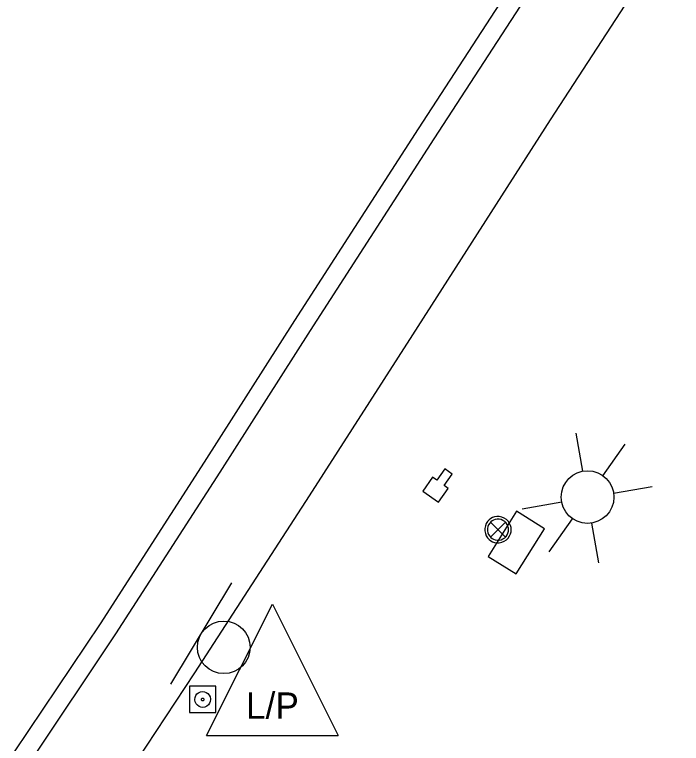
# Model space of a CAD drawing. Extents: x 2161152 to 2175754, y 602179 to 617749.
# Drawn here: x 2162247.2 to 2162297.9, y 604333.2 to 604388.6 of the extents above; entities that cross this region are included whole.
import ezdxf

# ---------------------------------------------------------------- set-up
doc = ezdxf.new("R2010")
doc.units = 0
for name, color, linetype in [('RD_EX_BldgApp_Post', 7, 'Continuous'), ('RD_EX_BldgApp_Sign', 7, 'Continuous'), ('RD_EX_Conc_Curb', 7, 'Continuous'), ('RD_EX_Conc_Gutter', 7, 'Continuous'), ('RD_EX_Conc_Sidewalk', 7, 'Continuous'), ('RD_EX_Misc', 7, 'Continuous'), ('RD_EX_UT', 7, 'Continuous')]:
    doc.layers.add(name, color=color, linetype=linetype)

msp = doc.modelspace()

# ---------------------------------------------------------------- linework, layer by layer
at = {"layer": 'RD_EX_BldgApp_Post'}
for p, q in [((2162284.499, 604348.864), (2162283.365, 604349.999)), ((2162283.365, 604348.864), (2162284.499, 604349.999))]:
    msp.add_line(p, q, dxfattribs=at)
for points in [[(2162284.935, 604349.431), (2162284.923, 604349.586), (2162284.883, 604349.749), (2162284.812, 604349.912), (2162284.707, 604350.068), (2162284.569, 604350.206), (2162284.405, 604350.316), (2162284.222, 604350.391), (2162284.033, 604350.429), (2162283.848, 604350.43), (2162283.676, 604350.401), (2162283.522, 604350.346), (2162283.388, 604350.273), (2162283.262, 604350.177), (2162283.145, 604350.052), (2162283.046, 604349.899), (2162282.973, 604349.723), (2162282.935, 604349.53), (2162282.935, 604349.333), (2162282.973, 604349.14), (2162283.046, 604348.964), (2162283.145, 604348.811), (2162283.262, 604348.686), (2162283.388, 604348.59), (2162283.522, 604348.517), (2162283.676, 604348.462), (2162283.848, 604348.433), (2162284.033, 604348.434), (2162284.222, 604348.472), (2162284.405, 604348.547), (2162284.569, 604348.657), (2162284.707, 604348.795), (2162284.812, 604348.951), (2162284.883, 604349.114), (2162284.923, 604349.277), (2162284.935, 604349.431)], [(2162284.734, 604349.431), (2162284.725, 604349.555), (2162284.693, 604349.685), (2162284.636, 604349.816), (2162284.552, 604349.941), (2162284.442, 604350.051), (2162284.31, 604350.139), (2162284.164, 604350.199), (2162284.013, 604350.229), (2162283.865, 604350.231), (2162283.727, 604350.207), (2162283.604, 604350.163), (2162283.497, 604350.105), (2162283.396, 604350.028), (2162283.302, 604349.928), (2162283.223, 604349.805), (2162283.165, 604349.664), (2162283.134, 604349.511), (2162283.134, 604349.352), (2162283.165, 604349.199), (2162283.223, 604349.058), (2162283.302, 604348.935), (2162283.396, 604348.835), (2162283.497, 604348.758), (2162283.604, 604348.7), (2162283.727, 604348.656), (2162283.865, 604348.632), (2162284.013, 604348.634), (2162284.164, 604348.664), (2162284.31, 604348.724), (2162284.442, 604348.812), (2162284.552, 604348.922), (2162284.636, 604349.047), (2162284.693, 604349.178), (2162284.725, 604349.308), (2162284.734, 604349.431)]]:
    msp.add_lwpolyline(points, dxfattribs=at)
at = {"layer": 'RD_EX_BldgApp_Sign'}
msp.add_line((2162263.706, 604345.4), (2162259.06, 604337.693), dxfattribs=at)
msp.add_circle((2162263.108, 604340.487), 2, dxfattribs=at)
at = {"layer": 'RD_EX_Conc_Curb'}
msp.add_lwpolyline([(2162248.396, 604331.757), (2162254.916, 604341.509), (2162262.836, 604353.795), (2162269.691, 604364.567), (2162279.076, 604379.145), (2162287.342, 604391.863), (2162296.136, 604405.511), (2162305.412, 604419.791), (2162313.247, 604431.9), (2162320.961, 604443.807), (2162329.033, 604456.25), (2162338.718, 604471.109), (2162347.938, 604485.433), (2162355.438, 604496.962)], dxfattribs=at)
at = {"layer": 'RD_EX_Conc_Gutter'}
msp.add_lwpolyline([(2162247.222, 604332.534), (2162253.738, 604342.282), (2162261.65, 604354.554), (2162268.504, 604365.326), (2162277.893, 604379.91), (2162286.159, 604392.628), (2162294.953, 604406.276), (2162304.23, 604420.557), (2162312.065, 604432.666), (2162319.779, 604444.573), (2162327.852, 604457.017), (2162337.535, 604471.875), (2162346.755, 604486.199), (2162354.255, 604497.728)], dxfattribs=at)
at = {"layer": 'RD_EX_Conc_Sidewalk'}
msp.add_lwpolyline([(2162255.048, 604329.619), (2162260.912, 604338.541), (2162269.608, 604351.999), (2162277.475, 604364.244), (2162287.918, 604380.572), (2162296.436, 604393.672), (2162305.935, 604408.262), (2162316.466, 604424.487), (2162326.823, 604440.641), (2162337.285, 604456.708), (2162347.116, 604471.828), (2162360.792, 604492.951), (2162374.627, 604514.304), (2162387.541, 604534.074), (2162401.099, 604555.258), (2162398.747, 604556.995), (2162396.101, 604558.592)], dxfattribs=at)
at = {"layer": 'RD_EX_Misc'}
for points in [[(2162260.505, 604335.526), (2162262.505, 604335.526), (2162262.505, 604337.526), (2162260.505, 604337.526), (2162260.505, 604335.526)], [(2162260.905, 604336.526), (2162260.925, 604336.678), (2162260.982, 604336.82), (2162261.074, 604336.943), (2162261.194, 604337.039), (2162261.334, 604337.101), (2162261.486, 604337.126), (2162261.639, 604337.111), (2162261.783, 604337.058), (2162261.909, 604336.97), (2162262.008, 604336.853), (2162262.075, 604336.715), (2162262.104, 604336.564), (2162262.105, 604336.526)], [(2162262.105, 604336.526), (2162262.085, 604336.375), (2162262.028, 604336.232), (2162261.936, 604336.11), (2162261.816, 604336.014), (2162261.676, 604335.951), (2162261.524, 604335.926), (2162261.371, 604335.941), (2162261.227, 604335.994), (2162261.101, 604336.082), (2162261.002, 604336.2), (2162260.935, 604336.338), (2162260.906, 604336.488), (2162260.905, 604336.526)], [(2162261.405, 604336.526), (2162261.424, 604336.585), (2162261.474, 604336.621), (2162261.536, 604336.621), (2162261.586, 604336.585), (2162261.605, 604336.526)], [(2162261.605, 604336.526), (2162261.586, 604336.467), (2162261.536, 604336.431), (2162261.474, 604336.431), (2162261.424, 604336.467), (2162261.405, 604336.526)]]:
    msp.add_lwpolyline(points, dxfattribs=at)
at = {"layer": 'RD_EX_UT'}
for p, q in [((2162289.853, 604356.771), (2162290.355, 604353.874)), ((2162291.899, 604353.536), (2162293.587, 604355.932)), ((2162295.633, 604352.698), (2162292.714, 604352.193)), ((2162288.775, 604351.51), (2162285.78, 604350.991)), ((2162287.827, 604347.758), (2162289.595, 604350.267)), ((2162291.038, 604349.934), (2162291.56, 604346.918)), ((2162261.804, 604333.777), (2162266.804, 604343.777)), ((2162266.804, 604343.777), (2162271.804, 604333.777)), ((2162261.804, 604333.777), (2162271.804, 604333.777))]:
    msp.add_line(p, q, dxfattribs=at)
for points in [[(2162278.224, 604352.363), (2162279.412, 604351.522), (2162280.15, 604352.564), (2162279.835, 604352.788), (2162280.453, 604353.661), (2162279.907, 604354.048), (2162279.294, 604353.183), (2162278.968, 604353.414), (2162278.224, 604352.363)], [(2162283.175, 604347.4), (2162285.302, 604346.063), (2162287.463, 604349.501), (2162285.336, 604350.838), (2162283.175, 604347.4)]]:
    msp.add_lwpolyline(points, dxfattribs=at)
msp.add_circle((2162290.734, 604351.91), 2, dxfattribs=at)

# ---------------------------------------------------------------- texts
msp.add_text('L/P', height=2, dxfattribs=at).set_placement((2162264.795, 604335.058))

doc.saveas('drawing.dxf')
